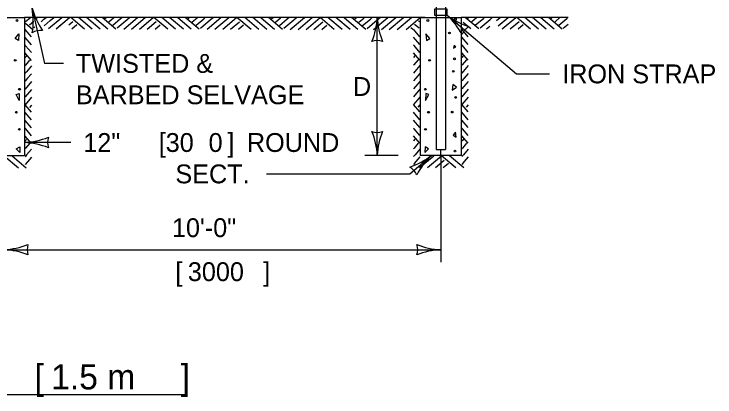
# Model space of a CAD drawing. Extents: x 49973.1 to 50021, y 49987.6 to 50015.4.
# Drawn here: x 49978.561 to 49980.792, y 50007.802 to 50009.022 of the extents above; entities that cross this region are included whole.
import ezdxf

# ---------------------------------------------------------------- set-up
doc = ezdxf.new("R2010")
doc.units = 0
for name, color, linetype in [('Level 1', 7, 'Continuous'), ('Level 2', 7, 'Continuous'), ('Level 3', 7, 'Continuous')]:
    doc.layers.add(name, color=color, linetype=linetype)

msp = doc.modelspace()

# ---------------------------------------------------------------- linework, layer by layer
at = {"layer": 'Level 1'}
for p, q in [((49979.9038, 50009.5855), (49979.9038, 50008.5907)), ((49979.9338, 50009.5855), (49979.9338, 50008.5907)), ((49978.4641, 50009.0107), (49978.5941, 50009.0107)), ((49979.8688, 50009.0107), (49978.5941, 50009.0107)), ((49978.5941, 50009.0107), (49978.5941, 50008.5716)), ((49978.5974, 50008.9978), (49978.6128, 50009.0106)), ((49978.6099, 50008.9873), (49978.6236, 50008.9988)), ((49978.6338, 50009.0073), (49978.6345, 50009.0079)), ((49978.6468, 50008.9972), (49978.6561, 50009.005)), ((49978.6561, 50009.005), (49978.6629, 50009.0106)), ((49978.6564, 50008.9843), (49978.6762, 50009.0008)), ((49978.6708, 50008.9754), (49978.7129, 50009.0106)), ((49978.6762, 50009.0008), (49978.6879, 50009.0106)), ((49978.6947, 50008.9745), (49978.7378, 50009.0106)), ((49978.7321, 50009.0058), (49978.7378, 50009.0106)), ((49978.7352, 50008.9875), (49978.7481, 50008.9983)), ((49978.7848, 50008.974), (49978.7413, 50009.0106)), ((49978.8098, 50008.974), (49978.7663, 50009.0106)), ((49978.8348, 50008.974), (49978.7913, 50009.0106)), ((49978.8168, 50009.0101), (49978.8163, 50009.0106)), ((49978.8598, 50008.974), (49978.8168, 50009.0101)), ((49978.8848, 50008.974), (49978.8413, 50009.0106)), ((49978.8498, 50009.0075), (49978.8535, 50009.0106)), ((49978.8625, 50008.9973), (49978.8782, 50009.0104)), ((49978.875, 50008.9868), (49978.8996, 50009.0074)), ((49978.8782, 50009.0104), (49978.8785, 50009.0106)), ((49978.8889, 50008.9774), (49978.9212, 50009.0045)), ((49978.8996, 50009.0074), (49978.9035, 50009.0106)), ((49978.9098, 50008.974), (49978.9536, 50009.0106)), ((49978.9212, 50009.0045), (49978.9286, 50009.0106)), ((49978.9348, 50008.974), (49978.9786, 50009.0106)), ((49978.9598, 50008.974), (49979.0035, 50009.0106)), ((49979.0499, 50008.9735), (49979.0058, 50009.0106)), ((49979.0749, 50008.9735), (49979.0308, 50009.0106)), ((49979.0999, 50008.9735), (49979.0558, 50009.0106)), ((49979.0819, 50009.0096), (49979.0808, 50009.0106)), ((49979.1249, 50008.9735), (49979.0819, 50009.0096)), ((49979.1499, 50008.9735), (49979.1058, 50009.0106)), ((49979.1149, 50009.007), (49979.1192, 50009.0106)), ((49979.1276, 50008.9968), (49979.1433, 50009.0099)), ((49979.1401, 50008.9863), (49979.1647, 50009.0069)), ((49979.1433, 50009.0099), (49979.1442, 50009.0106)), ((49979.154, 50008.9769), (49979.1863, 50009.004)), ((49979.1647, 50009.0069), (49979.1692, 50009.0106)), ((49979.1749, 50008.9735), (49979.2193, 50009.0106)), ((49979.1863, 50009.004), (49979.1943, 50009.0106)), ((49979.1999, 50008.9735), (49979.2443, 50009.0106)), ((49979.2249, 50008.9735), (49979.2692, 50009.0106)), ((49979.315, 50008.973), (49979.2703, 50009.0106)), ((49979.34, 50008.973), (49979.2953, 50009.0106)), ((49979.365, 50008.973), (49979.3203, 50009.0106)), ((49979.347, 50009.0091), (49979.3453, 50009.0106)), ((49979.39, 50008.973), (49979.347, 50009.0091)), ((49979.415, 50008.973), (49979.3703, 50009.0106)), ((49979.38, 50009.0065), (49979.385, 50009.0107)), ((49979.3927, 50008.9963), (49979.4084, 50009.0094)), ((49979.4052, 50008.9858), (49979.4298, 50009.0064)), ((49979.4084, 50009.0094), (49979.4099, 50009.0106)), ((49979.4191, 50008.9764), (49979.4514, 50009.0035)), ((49979.4298, 50009.0064), (49979.4349, 50009.0106)), ((49979.44, 50008.973), (49979.485, 50009.0106)), ((49979.4514, 50009.0035), (49979.46, 50009.0106)), ((49979.465, 50008.973), (49979.51, 50009.0106)), ((49979.49, 50008.973), (49979.5348, 50009.0106)), ((49979.5801, 50008.9725), (49979.5348, 50009.0106)), ((49979.6051, 50008.9725), (49979.5598, 50009.0106)), ((49979.6301, 50008.9725), (49979.5848, 50009.0106)), ((49979.6121, 50009.0086), (49979.6098, 50009.0106)), ((49979.6551, 50008.9725), (49979.6121, 50009.0086)), ((49979.6801, 50008.9725), (49979.6348, 50009.0106)), ((49979.6451, 50009.006), (49979.6501, 50009.0102)), ((49979.6501, 50009.0102), (49979.6506, 50009.0106)), ((49979.6578, 50008.9958), (49979.6735, 50009.0089)), ((49979.6703, 50008.9853), (49979.6949, 50009.0059)), ((49979.6735, 50009.0089), (49979.6756, 50009.0106)), ((49979.6842, 50008.9759), (49979.7165, 50009.003)), ((49979.6949, 50009.0059), (49979.7006, 50009.0106)), ((49979.7051, 50008.9725), (49979.7506, 50009.0106)), ((49979.7165, 50009.003), (49979.7257, 50009.0106)), ((49979.7301, 50008.9725), (49979.7756, 50009.0106)), ((49979.7551, 50008.9725), (49979.8005, 50009.0106)), ((49979.7801, 50008.9725), (49979.8256, 50009.0106)), ((49979.8083, 50008.9726), (49979.8538, 50009.0107)), ((49979.8512, 50008.9968), (49979.8477, 50008.9997)), ((49979.8538, 50009.0107), (49979.8538, 50008.5716)), ((49979.8538, 50009.0107), (49979.9838, 50009.0107)), ((49979.9838, 50009.0107), (49979.9838, 50008.5716)), ((49980.3238, 50009.0106), (49979.9838, 50009.0106)), ((49980.0397, 50008.9744), (49979.9968, 50009.0105)), ((49980.0047, 50009.0079), (49980.0078, 50009.0105)), ((49980.0174, 50008.9977), (49980.0328, 50009.0105)), ((49980.0299, 50008.9872), (49980.0545, 50009.0078)), ((49980.0438, 50008.9778), (49980.0761, 50009.0049)), ((49980.0545, 50009.0078), (49980.0578, 50009.0105)), ((49980.0761, 50009.0049), (49980.0829, 50009.0105)), ((49980.0962, 50009.0007), (49980.1079, 50009.0105)), ((49980.1018, 50008.9845), (49980.1329, 50009.0105)), ((49980.1147, 50008.9744), (49980.1578, 50009.0105)), ((49980.1147, 50008.9744), (49980.1578, 50009.0105)), ((49980.2048, 50008.9739), (49980.1613, 50009.0105)), ((49980.2298, 50008.9739), (49980.1863, 50009.0105)), ((49980.2548, 50008.9739), (49980.2113, 50009.0105)), ((49980.2798, 50008.9739), (49980.2368, 50009.01)), ((49980.3048, 50008.9739), (49980.2613, 50009.0105)), ((49980.2698, 50009.0074), (49980.2735, 50009.0105)), ((49980.2825, 50008.9972), (49980.2982, 50009.0103)), ((49980.295, 50008.9867), (49980.3196, 50009.0073)), ((49980.3196, 50009.0073), (49980.3235, 50009.0105)), ((49978.6218, 50008.9709), (49978.5972, 50008.9915)), ((49978.6238, 50008.9779), (49978.627, 50008.9807)), ((49978.6947, 50008.9745), (49978.7121, 50008.9891)), ((49978.7447, 50008.9745), (49978.761, 50008.9882)), ((49978.9848, 50008.974), (49979.0132, 50008.9978)), ((49979.0098, 50008.974), (49979.0261, 50008.9877)), ((49979.2499, 50008.9735), (49979.2783, 50008.9973)), ((49979.2749, 50008.9735), (49979.2912, 50008.9872)), ((49979.515, 50008.973), (49979.5434, 50008.9968)), ((49979.54, 50008.973), (49979.5563, 50008.9867)), ((49979.8301, 50008.9725), (49979.8233, 50008.9782)), ((49979.85, 50008.9768), (49979.8356, 50008.9888)), ((49980.0147, 50008.9744), (49979.9901, 50008.995)), ((49980.0647, 50008.9744), (49980.0751, 50008.9831)), ((49980.1397, 50008.9744), (49980.1681, 50008.9982)), ((49980.1647, 50008.9744), (49980.181, 50008.9881)), ((49980.3089, 50008.9773), (49980.3238, 50008.9898)), ((49978.6159, 50008.9489), (49978.596, 50008.9726)), ((49979.8521, 50008.9496), (49979.8322, 50008.9733)), ((49980.0061, 50008.9496), (49979.9862, 50008.9733)), ((49979.9897, 50008.9744), (49979.9884, 50008.9755)), ((49978.6159, 50008.9239), (49978.596, 50008.9476)), ((49979.8521, 50008.9246), (49979.8322, 50008.9483)), ((49980.0061, 50008.9246), (49979.9862, 50008.9483)), ((49978.5975, 50008.9209), (49978.596, 50008.9226)), ((49978.6159, 50008.8989), (49978.5975, 50008.9209)), ((49979.8337, 50008.9216), (49979.8322, 50008.9233)), ((49979.8521, 50008.8996), (49979.8337, 50008.9216)), ((49979.9877, 50008.9216), (49979.9862, 50008.9233)), ((49980.0061, 50008.8996), (49979.9877, 50008.9216)), ((49978.6001, 50008.8879), (49978.5959, 50008.8829)), ((49978.6159, 50008.8739), (49978.596, 50008.8976)), ((49979.8363, 50008.8886), (49979.8321, 50008.8836)), ((49979.8521, 50008.8746), (49979.8322, 50008.8983)), ((49979.9903, 50008.8886), (49979.9861, 50008.8836)), ((49980.0061, 50008.8746), (49979.9862, 50008.8983)), ((49978.6103, 50008.8752), (49978.5972, 50008.8595)), ((49979.8465, 50008.8759), (49979.8334, 50008.8602)), ((49980.0005, 50008.8759), (49979.9874, 50008.8602)), ((49978.5972, 50008.8595), (49978.596, 50008.858)), ((49978.6159, 50008.8568), (49978.6002, 50008.8381)), ((49979.8334, 50008.8602), (49979.8322, 50008.8587)), ((49979.8521, 50008.8575), (49979.8364, 50008.8388)), ((49979.9874, 50008.8602), (49979.9862, 50008.8587)), ((49980.0061, 50008.8575), (49979.9904, 50008.8388)), ((49978.6002, 50008.8381), (49978.596, 50008.833)), ((49978.6159, 50008.8317), (49978.6031, 50008.8165)), ((49979.8364, 50008.8388), (49979.8322, 50008.8337)), ((49979.8521, 50008.8324), (49979.8393, 50008.8172)), ((49979.9904, 50008.8388), (49979.9862, 50008.8337)), ((49980.0061, 50008.8324), (49979.9933, 50008.8172)), ((49978.6031, 50008.8165), (49978.596, 50008.8079)), ((49978.6159, 50008.8067), (49978.596, 50008.7829)), ((49979.8393, 50008.8172), (49979.8322, 50008.8086)), ((49979.8521, 50008.8074), (49979.8322, 50008.7836)), ((49979.9933, 50008.8172), (49979.9862, 50008.8086)), ((49980.0061, 50008.8074), (49979.9862, 50008.7836)), ((49978.6159, 50008.7817), (49978.596, 50008.7579)), ((49979.8521, 50008.7824), (49979.8322, 50008.7586)), ((49980.0061, 50008.7824), (49979.9862, 50008.7586)), ((49978.6159, 50008.7568), (49978.596, 50008.7331)), ((49979.8521, 50008.7575), (49979.8322, 50008.7338)), ((49980.0061, 50008.7575), (49979.9862, 50008.7338)), ((49978.6159, 50008.7094), (49978.596, 50008.7331)), ((49978.6159, 50008.7317), (49978.6098, 50008.7245)), ((49979.8521, 50008.7101), (49979.8322, 50008.7338)), ((49979.8521, 50008.7324), (49979.846, 50008.7252)), ((49980.0061, 50008.7101), (49979.9862, 50008.7338)), ((49980.0061, 50008.7324), (49980, 50008.7252)), ((49979.8521, 50008.6851), (49979.8322, 50008.7088)), ((49980.0061, 50008.6851), (49979.9862, 50008.7088)), ((49978.6159, 50008.6844), (49978.596, 50008.7081)), ((49978.6159, 50008.6594), (49978.596, 50008.6831)), ((49979.8521, 50008.6601), (49979.8322, 50008.6838)), ((49980.0061, 50008.6601), (49979.9862, 50008.6838)), ((49978.598, 50008.6558), (49978.596, 50008.6581)), ((49978.6159, 50008.6344), (49978.598, 50008.6558)), ((49979.8342, 50008.6565), (49979.8322, 50008.6588)), ((49979.8521, 50008.6351), (49979.8342, 50008.6565)), ((49979.9882, 50008.6565), (49979.9862, 50008.6588)), ((49980.0061, 50008.6351), (49979.9882, 50008.6565)), ((49978.6159, 50008.6094), (49978.596, 50008.6331)), ((49978.6006, 50008.6228), (49978.5964, 50008.6178)), ((49979.8521, 50008.6101), (49979.8322, 50008.6338)), ((49979.8368, 50008.6235), (49979.8326, 50008.6185)), ((49980.0061, 50008.6101), (49979.9862, 50008.6338)), ((49979.9908, 50008.6235), (49979.9866, 50008.6185)), ((49978.5964, 50008.6178), (49978.596, 50008.6173)), ((49978.6108, 50008.6101), (49978.5977, 50008.5944)), ((49979.8326, 50008.6185), (49979.8322, 50008.618)), ((49979.847, 50008.6108), (49979.8339, 50008.5951)), ((49979.9866, 50008.6185), (49979.9862, 50008.618)), ((49980.001, 50008.6108), (49979.9879, 50008.5951)), ((49978.5977, 50008.5944), (49978.596, 50008.5923)), ((49978.6159, 50008.5911), (49978.6007, 50008.573)), ((49979.8339, 50008.5951), (49979.8322, 50008.593)), ((49979.8521, 50008.5918), (49979.8369, 50008.5737)), ((49979.9038, 50008.5907), (49979.9338, 50008.5907)), ((49979.9879, 50008.5951), (49979.9862, 50008.593)), ((49980.0061, 50008.5918), (49979.9909, 50008.5737)), ((49978.4641, 50008.5716), (49978.5941, 50008.5716)), ((49978.5748, 50008.5306), (49978.5295, 50008.5687)), ((49978.5998, 50008.5306), (49978.5545, 50008.5687)), ((49978.6007, 50008.573), (49978.596, 50008.5673)), ((49978.6159, 50008.566), (49978.6036, 50008.5514)), ((49979.8369, 50008.5737), (49979.8322, 50008.568)), ((49979.8521, 50008.5667), (49979.8398, 50008.5521)), ((49979.8517, 50008.5328), (49979.8967, 50008.5704)), ((49979.9838, 50008.5716), (49979.8538, 50008.5716)), ((49979.8767, 50008.5328), (49979.9215, 50008.5704)), ((49979.9017, 50008.5328), (49979.9301, 50008.5566)), ((49979.9668, 50008.5323), (49979.9215, 50008.5704)), ((49979.9918, 50008.5323), (49979.9465, 50008.5704)), ((49979.9909, 50008.5737), (49979.9862, 50008.568)), ((49980.0061, 50008.5667), (49979.9938, 50008.5521)), ((49978.6036, 50008.5514), (49978.596, 50008.5422)), ((49979.8398, 50008.5521), (49979.8322, 50008.5429)), ((49979.9267, 50008.5328), (49979.943, 50008.5465)), ((49979.9938, 50008.5521), (49979.9862, 50008.5429))]:
    msp.add_line(p, q, dxfattribs=at)
for points in [[(49979.8989, 50009.0377), (49979.8989, 50009.0179), (49979.939, 50009.0179), (49979.939, 50009.0377)], [(49978.5639, 50008.9444), (49978.5763, 50008.9588), (49978.5749, 50008.9376)], [(49979.884, 50008.9444), (49979.8716, 50008.9588), (49979.873, 50008.9376)], [(49979.9663, 50008.917), (49979.9615, 50008.9232), (49979.9595, 50008.9136)], [(49979.9684, 50008.7894), (49979.9574, 50008.7976), (49979.9553, 50008.7797)], [(49978.5673, 50008.7653), (49978.5769, 50008.7688), (49978.5776, 50008.7461)], [(49979.8806, 50008.7653), (49979.871, 50008.7688), (49979.8703, 50008.7461)], [(49979.9677, 50008.6302), (49979.9656, 50008.6459), (49979.9588, 50008.6357)], [(49978.568, 50008.5924), (49978.579, 50008.5993), (49978.5797, 50008.5808)], [(49979.8799, 50008.5924), (49979.8689, 50008.5993), (49979.8682, 50008.5808)]]:
    msp.add_lwpolyline(points, close=True, dxfattribs=at)
for centre in [(49978.5701, 50009.0013), (49979.8778, 50009.0013), (49979.9656, 50009.0054), (49979.9464, 50008.9615), (49978.5646, 50008.8744), (49979.8833, 50008.8744), (49979.9622, 50008.8792), (49979.9588, 50008.8394), (49978.5783, 50008.7824), (49979.8696, 50008.7824), (49979.9663, 50008.7563), (49978.5681, 50008.709), (49979.8798, 50008.709), (49979.9553, 50008.7097), (49978.5777, 50008.6548), (49979.8702, 50008.6548), (49979.9642, 50008.5855)]:
    msp.add_circle(centre, 0.00279, dxfattribs=at)
at = {"layer": 'Level 2'}
msp.add_lwpolyline([(49976.5238, 50007.8105), (49979.1061, 50007.8105)], dxfattribs=at)
at = {"layer": 'Level 3'}
for p, q in [((49978.6184, 50009.04), (49978.6578, 50008.8646)), ((49979.7167, 50008.5716), (49979.7167, 50009.0107)), ((49979.939, 50009.0179), (49980.1594, 50008.8312)), ((49978.7177, 50008.8646), (49978.6578, 50008.8646)), ((49980.1594, 50008.8312), (49980.2654, 50008.8312)), ((49978.7412, 50008.6127), (49978.5941, 50008.6127)), ((49979.9188, 50008.5716), (49979.9188, 50008.5907)), ((49979.7831, 50008.5716), (49979.6767, 50008.5716)), ((49979.82, 50008.5127), (49979.8889, 50008.5716)), ((49979.9188, 50008.5716), (49979.9188, 50008.2314)), ((49979.3638, 50008.5127), (49979.82, 50008.5127)), ((49978.5291, 50008.2714), (49979.9188, 50008.2714))]:
    msp.add_line(p, q, dxfattribs=at)
for centre, radius, start, end in [((49978.3997, 50009.0003), 0.2223, 350.101, 10.2845), ((49978.843, 50009.1022), 0.233, 195.4723, 214.7222), ((49979.4946, 50009.0199), 0.2223, 337.456, 357.6395), ((49979.9494, 50009.0222), 0.233, 182.8273, 202.0772), ((49979.7898, 50008.8531), 0.2223, 27.66, 47.8435), ((49980.0791, 50009.2041), 0.233, 233.0313, 252.2812), ((49980.0375, 50008.9359), 0.0548, 122.3428, 158.0652), ((49978.6465, 50008.9149), 0.0548, 84.7838, 120.5062), ((49979.7167, 50008.8825), 0.0548, 72.1388, 107.8612), ((49979.7167, 50008.6998), 0.0548, 252.1388, 287.8612), ((49979.484, 50008.5601), 0.233, 2.8273, 22.0772), ((49979.9388, 50008.5625), 0.2223, 157.456, 177.6395), ((49978.5826, 50008.8454), 0.233, 272.8273, 292.0772), ((49978.7223, 50008.6127), 0.0548, 162.1388, 197.8612), ((49978.5849, 50008.3906), 0.2223, 67.456, 87.6395), ((49979.7507, 50008.7458), 0.2223, 288.2484, 308.4319), ((49980.0496, 50008.403), 0.233, 133.6197, 152.8695), ((49979.7918, 50008.4879), 0.0548, 22.9312, 58.6536), ((49978.5176, 50008.5041), 0.233, 272.8273, 292.0772), ((49978.6573, 50008.2714), 0.0548, 162.1388, 197.8612), ((49979.928, 50008.4936), 0.2223, 247.456, 267.6395), ((49979.7906, 50008.2714), 0.0548, 342.1388, 17.8612), ((49978.5199, 50008.0493), 0.2223, 67.456, 87.6395), ((49979.9303, 50008.0387), 0.233, 92.8273, 112.0772)]:
    msp.add_arc(centre, radius, start, end, dxfattribs=at)

# ---------------------------------------------------------------- texts
at = {"layer": 'Level 2'}
for s, height, p in [('TWISTED &', 0.06, (49978.7577, 50008.8346)), ('IRON STRAP', 0.06, (49980.3054, 50008.8012)), ('D', 0.06, (49979.6394, 50008.7611)), ('BARBED SELVAGE', 0.06, (49978.7577, 50008.7346)), ('12" ', 0.06, (49978.7812, 50008.5827)), ('[30', 0.06, (49979.0212, 50008.5827)), ('0', 0.06, (49979.1799, 50008.5827)), (']', 0.06, (49979.2399, 50008.5827)), (' ROUND', 0.06, (49979.2796, 50008.5827)), ('SECT.', 0.06, (49979.0743, 50008.4827)), ('10\'-0"', 0.06, (49979.0633, 50008.3114)), ('[', 0.06, (49979.0742, 50008.1714)), ('3000', 0.06, (49979.1139, 50008.1714)), (']', 0.06, (49979.3539, 50008.1714)), ('[', 0.08, (49978.6261, 50007.8265)), ('1.5 m', 0.08, (49978.679, 50007.8265)), (']', 0.08, (49979.0909, 50007.8265))]:
    msp.add_text(s, height=height, dxfattribs=at).set_placement(p)

doc.saveas('drawing.dxf')
